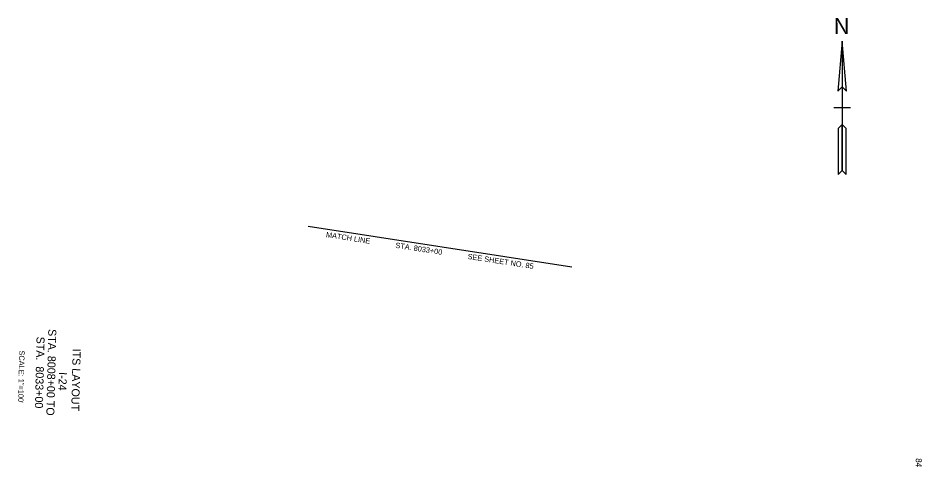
# Model space of a CAD drawing. Extents: x -200 to 1755004, y -325 to 657649.
# Drawn here: x 1752972 to 1755004, y 654618 to 655627 of the extents above; entities that cross this region are included whole.
import ezdxf

# ---------------------------------------------------------------- set-up
doc = ezdxf.new("R2010")
doc.units = 0
for name, color, linetype in [('DESIGN - CENTERLINE - Proposed Text', 7, 'Continuous'), ('DESIGN - SCRATCH - User 1', 7, 'Continuous'), ('DESIGN - SHEET - Corner Text', 7, 'Continuous'), ('ITS - CONST TEXT', 7, 'Continuous'), ('ITS - EXISTING COMM CABLE', 7, 'Continuous'), ('ITS - EXISTING HAR', 7, 'Continuous')]:
    doc.layers.add(name, color=color, linetype=linetype)

msp = doc.modelspace()

# ---------------------------------------------------------------- linework, layer by layer
at = {"layer": 'DESIGN - CENTERLINE - Proposed Text'}
for p, q in [((1754824.8, 655425.8), (1754805.9, 655425.8)), ((1754843.7, 655425.8), (1754824.8, 655425.8))]:
    msp.add_line(p, q, dxfattribs=at)
msp.add_lwpolyline([(1754824.8, 655575.8), (1754815, 655463.2), (1754824.8, 655473), (1754834.6, 655463.2), (1754824.8, 655575.8), (1754824.8, 655284.9), (1754833.9, 655275.8), (1754833.9, 655379.3), (1754824.8, 655388.4), (1754815.7, 655379.3), (1754815.7, 655275.8), (1754824.8, 655284.9)], dxfattribs=at)
for points in [[(1754824.8, 655473), (1754834.6, 655463.2), (1754824.8, 655575.8)], [(1754815.7, 655275.8), (1754824.8, 655284.9), (1754824.8, 655388.4), (1754815.7, 655379.3)]]:
    msp.add_lwpolyline(points, close=True, dxfattribs=at)
at = {"layer": 'DESIGN - SCRATCH - User 1'}
msp.add_line((1753047.9, 654799.8), (1753047.9, 654799.8), dxfattribs=at)
msp.add_line((1753047.9, 654799.8), (1753047.9, 654799.8), dxfattribs=at)
at = {"layer": 'ITS - EXISTING COMM CABLE'}
msp.add_line((1753624.2, 655159.3), (1754217.2, 655068), dxfattribs=at)

# ---------------------------------------------------------------- texts
at = {"layer": 'DESIGN - CENTERLINE - Proposed Text'}
msp.add_text('N', height=35.4, dxfattribs=at).set_placement((1754806.7, 655591.9))
at = {"layer": 'DESIGN - SHEET - Corner Text'}
msp.add_text('84', height=13.5, rotation=268.6447, dxfattribs=at).set_placement((1754990.7, 654637.9))
at = {"layer": 'ITS - CONST TEXT'}
msp.add_text('SCALE: 1"=100\'', height=12, rotation=268.6447, dxfattribs=at).set_placement((1752974.6, 654880.1))
at = {"layer": 'ITS - EXISTING COMM CABLE'}
for s, p in [('MATCH LINE', (1753663.6, 655135)), ('STA. 8033+00', (1753819.7, 655111)), ('SEE SHEET NO. 85 ', (1753982, 655086))]:
    msp.add_text(s, height=12, rotation=351.2527, dxfattribs=at).set_placement(p)
at = {"layer": 'ITS - EXISTING HAR'}
for s, p in [('STA. 8008+00 TO', (1753039.9, 654928.3)), ('STA.  8033+00', (1753013.5, 654911.3)), ('ITS LAYOUT', (1753094.7, 654884.3)), ('I-24', (1753063.6, 654831.5))]:
    msp.add_text(s, height=18, rotation=268.6447, dxfattribs=at).set_placement(p)

doc.saveas('drawing.dxf')
